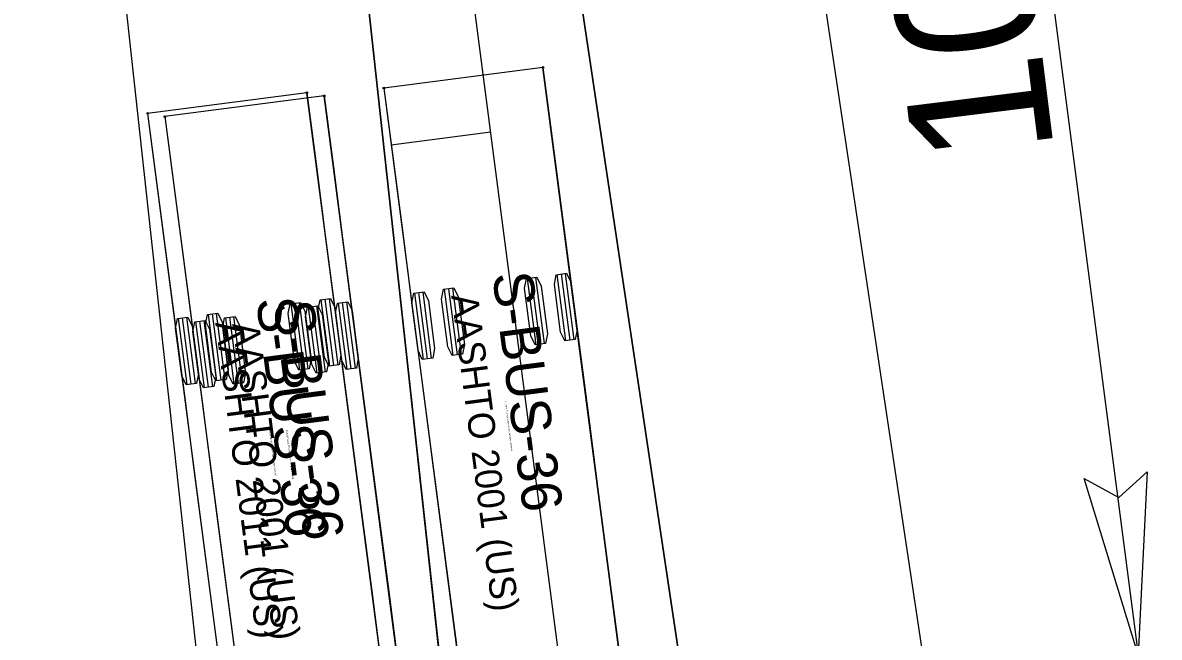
# Model space of a CAD drawing. Extents: x 2367848 to 2369479, y 800728 to 808616.
# Drawn here: x 2368338.9 to 2368395.5, y 808074.3 to 808105 of the extents above; entities that cross this region are included whole.
import ezdxf

# ---------------------------------------------------------------- set-up
doc = ezdxf.new("R2010")
doc.units = 0
for name, color, linetype in [('Prop AutoTurn Simulation', 7, 'Continuous'), ('Prop Dimension', 7, 'Continuous'), ('Prop EOT', 7, 'Continuous'), ('Prop Horizontal Alignment', 7, 'Continuous'), ('Prop Horizontal Alignment Tick Small', 7, 'Continuous'), ('Prop Lane Lines', 7, 'Continuous'), ('Prop Paint Stripe', 7, 'Continuous'), ('Prop Terminator CELL', 7, 'Continuous'), ('Scratch_Level_1', 7, 'Continuous')]:
    doc.layers.add(name, color=color, linetype=linetype)

msp = doc.modelspace()

# ---------------------------------------------------------------- linework, layer by layer
at = {"layer": 'Prop AutoTurn Simulation'}
for p, q in [((2368364.825, 808102.755), (2368356.892, 808101.723)), ((2368369.447, 808067.255), (2368364.825, 808102.755)), ((2368356.892, 808101.723), (2368361.514, 808066.222)), ((2368353.917, 808101.335), (2368345.984, 808100.302)), ((2368358.539, 808065.835), (2368353.917, 808101.335)), ((2368345.984, 808100.302), (2368350.606, 808064.802)), ((2368365.97, 808089.122), (2368365.54, 808092.428)), ((2368366.177, 808089.149), (2368365.746, 808092.455)), ((2368366.383, 808089.176), (2368365.953, 808092.482)), ((2368364.483, 808088.929), (2368364.052, 808092.234)), ((2368364.689, 808088.956), (2368364.259, 808092.261)), ((2368364.896, 808088.983), (2368364.465, 808092.288)), ((2368358.863, 808088.197), (2368358.433, 808091.503)), ((2368359.07, 808088.224), (2368358.64, 808091.53)), ((2368359.277, 808088.251), (2368358.846, 808091.556)), ((2368360.351, 808088.391), (2368359.92, 808091.696)), ((2368360.557, 808088.418), (2368360.127, 808091.723)), ((2368360.764, 808088.445), (2368360.334, 808091.75)), ((2368353.575, 808087.509), (2368353.144, 808090.814)), ((2368353.781, 808087.536), (2368353.351, 808090.841)), ((2368353.988, 808087.562), (2368353.558, 808090.868)), ((2368355.062, 808087.702), (2368354.632, 808091.008)), ((2368355.269, 808087.729), (2368354.838, 808091.035)), ((2368355.475, 808087.756), (2368355.045, 808091.062)), ((2368349.443, 808086.971), (2368349.013, 808090.276)), ((2368349.649, 808086.998), (2368349.219, 808090.303)), ((2368349.856, 808087.024), (2368349.426, 808090.33)), ((2368347.955, 808086.777), (2368347.525, 808090.082)), ((2368348.162, 808086.804), (2368347.732, 808090.109)), ((2368348.369, 808086.831), (2368347.938, 808090.136))]:
    msp.add_line(p, q, dxfattribs=at)
for points in [[(2368364.825, 808102.755), (2368365.288, 808099.205), (2368365.75, 808095.655), (2368366.212, 808092.105), (2368366.674, 808088.555), (2368367.136, 808085.005), (2368367.599, 808081.455), (2368368.061, 808077.905), (2368368.523, 808074.355), (2368368.985, 808070.805)], [(2368356.892, 808101.723), (2368357.355, 808098.173), (2368357.817, 808094.623), (2368358.279, 808091.072), (2368358.741, 808087.522), (2368359.203, 808083.972), (2368359.666, 808080.422), (2368360.128, 808076.872), (2368360.59, 808073.322)], [(2368353.917, 808101.335), (2368354.38, 808097.785), (2368354.842, 808094.235), (2368355.304, 808090.685), (2368355.766, 808087.135), (2368356.228, 808083.585), (2368356.691, 808080.035), (2368357.153, 808076.485), (2368357.615, 808072.935)], [(2368345.984, 808100.302), (2368346.447, 808096.752), (2368346.909, 808093.202), (2368347.371, 808089.652), (2368347.833, 808086.102), (2368348.295, 808082.552), (2368348.758, 808079.002), (2368349.22, 808075.452), (2368349.682, 808071.902)]]:
    msp.add_lwpolyline(points, dxfattribs=at)
for points in [[(2368366.434, 808089.183), (2368365.919, 808089.116), (2368365.703, 808089.558), (2368365.393, 808091.938), (2368365.488, 808092.421), (2368366.004, 808092.488), (2368366.22, 808092.046), (2368366.53, 808089.666)], [(2368364.947, 808088.989), (2368364.431, 808088.922), (2368364.216, 808089.365), (2368363.906, 808091.745), (2368364.001, 808092.228), (2368364.517, 808092.295), (2368364.732, 808091.852), (2368365.042, 808089.472)], [(2368359.328, 808088.258), (2368358.812, 808088.191), (2368358.597, 808088.633), (2368358.287, 808091.013), (2368358.382, 808091.496), (2368358.897, 808091.563), (2368359.113, 808091.121), (2368359.423, 808088.741)], [(2368360.815, 808088.451), (2368360.3, 808088.384), (2368360.084, 808088.827), (2368359.774, 808091.207), (2368359.869, 808091.69), (2368360.385, 808091.757), (2368360.6, 808091.314), (2368360.91, 808088.934)], [(2368354.039, 808087.569), (2368353.523, 808087.502), (2368353.308, 808087.944), (2368352.998, 808090.324), (2368353.093, 808090.807), (2368353.609, 808090.875), (2368353.824, 808090.432), (2368354.134, 808088.052)], [(2368355.527, 808087.763), (2368355.011, 808087.696), (2368354.795, 808088.138), (2368354.485, 808090.518), (2368354.581, 808091.001), (2368355.096, 808091.068), (2368355.312, 808090.626), (2368355.622, 808088.246)], [(2368349.907, 808087.031), (2368349.392, 808086.964), (2368349.176, 808087.407), (2368348.866, 808089.786), (2368348.961, 808090.269), (2368349.477, 808090.337), (2368349.693, 808089.894), (2368350.002, 808087.514)], [(2368348.42, 808086.837), (2368347.904, 808086.77), (2368347.689, 808087.213), (2368347.379, 808089.593), (2368347.474, 808090.076), (2368347.989, 808090.143), (2368348.205, 808089.7), (2368348.515, 808087.32)]]:
    msp.add_lwpolyline(points, close=True, dxfattribs=at)
for centre in [(2368364.825, 808102.755), (2368356.892, 808101.723), (2368353.917, 808101.335), (2368345.984, 808100.302)]:
    msp.add_circle(centre, 0.0417, dxfattribs=at)
at = {"layer": 'Prop Dimension'}
msp.add_line((2368381.576, 808172.631), (2368394.487, 808073.468), dxfattribs=at)
at = {"layer": 'Prop EOT'}
for p, q in [((2368339.442, 808368.833), (2368383.944, 808072.095)), ((2368348.245, 808067.447), (2368315.576, 808365.726))]:
    msp.add_line(p, q, dxfattribs=at)
at = {"layer": 'Prop Horizontal Alignment'}
msp.add_line((2368427.272, 807599.886), (2368315.244, 808460.338), dxfattribs=at)
at = {"layer": 'Prop Horizontal Alignment Tick Small'}
msp.add_line((2368362.221, 808099.52), (2368357.263, 808098.875), dxfattribs=at)
at = {"layer": 'Prop Lane Lines'}
for p, q in [((2368360.202, 808068.573), (2368327.531, 808366.851)), ((2368327.595, 808366.859), (2368372.044, 808070.546)), ((2368360.202, 808068.573), (2368349.265, 808168.424))]:
    msp.add_line(p, q, dxfattribs=at)
at = {"layer": 'Prop Paint Stripe'}
for p, q in [((2368372.044, 808070.546), (2368327.595, 808366.859)), ((2368372.044, 808070.546), (2368327.595, 808366.859)), ((2368349.265, 808168.424), (2368360.202, 808068.573))]:
    msp.add_line(p, q, dxfattribs=at)
msp.add_lwpolyline([(2368327.531, 808366.851), (2368349.265, 808168.424), (2368360.202, 808068.573)], dxfattribs=at)
at = {"layer": 'Prop Terminator CELL'}
msp.add_lwpolyline([(2368394.936, 808082.589), (2368394.487, 808073.468), (2368391.803, 808082.258), (2368393.53, 808081.31)], close=True, dxfattribs=at)
at = {"layer": 'Scratch_Level_1'}
for p, q in [((2368353.054, 808101.496), (2368345.121, 808100.463)), ((2368357.676, 808065.996), (2368353.054, 808101.496)), ((2368345.121, 808100.463), (2368349.743, 808064.963)), ((2368352.711, 808087.669), (2368352.281, 808090.975)), ((2368352.918, 808087.696), (2368352.487, 808091.002)), ((2368353.124, 808087.723), (2368352.694, 808091.029)), ((2368354.198, 808087.863), (2368353.768, 808091.168)), ((2368354.405, 808087.89), (2368353.975, 808091.195)), ((2368354.612, 808087.917), (2368354.181, 808091.222)), ((2368347.092, 808086.938), (2368346.661, 808090.243)), ((2368347.298, 808086.965), (2368346.868, 808090.27)), ((2368347.505, 808086.991), (2368347.075, 808090.297)), ((2368348.579, 808087.131), (2368348.149, 808090.437)), ((2368348.786, 808087.158), (2368348.355, 808090.464)), ((2368348.992, 808087.185), (2368348.562, 808090.491))]:
    msp.add_line(p, q, dxfattribs=at)
for points in [[(2368353.054, 808101.496), (2368353.516, 808097.946), (2368353.978, 808094.396), (2368354.44, 808090.846), (2368354.903, 808087.296), (2368355.365, 808083.746), (2368355.827, 808080.196), (2368356.289, 808076.646), (2368356.751, 808073.096)], [(2368345.121, 808100.463), (2368345.583, 808096.913), (2368346.045, 808093.363), (2368346.507, 808089.813), (2368346.969, 808086.263), (2368347.432, 808082.713), (2368347.894, 808079.163), (2368348.356, 808075.613), (2368348.818, 808072.063)]]:
    msp.add_lwpolyline(points, dxfattribs=at)
for points in [[(2368353.175, 808087.73), (2368352.66, 808087.663), (2368352.444, 808088.105), (2368352.134, 808090.485), (2368352.229, 808090.968), (2368352.745, 808091.035), (2368352.961, 808090.593), (2368353.27, 808088.213)], [(2368354.663, 808087.923), (2368354.147, 808087.856), (2368353.932, 808088.299), (2368353.622, 808090.679), (2368353.717, 808091.162), (2368354.232, 808091.229), (2368354.448, 808090.786), (2368354.758, 808088.406)], [(2368347.556, 808086.998), (2368347.041, 808086.931), (2368346.825, 808087.374), (2368346.515, 808089.753), (2368346.61, 808090.236), (2368347.126, 808090.304), (2368347.341, 808089.861), (2368347.651, 808087.481)], [(2368349.044, 808087.192), (2368348.528, 808087.125), (2368348.312, 808087.567), (2368348.002, 808089.947), (2368348.098, 808090.43), (2368348.613, 808090.497), (2368348.829, 808090.055), (2368349.139, 808087.675)]]:
    msp.add_lwpolyline(points, close=True, dxfattribs=at)
for centre in [(2368353.054, 808101.496), (2368345.121, 808100.463)]:
    msp.add_circle(centre, 0.0417, dxfattribs=at)

# ---------------------------------------------------------------- texts
at = {"layer": 'Prop AutoTurn Simulation'}
for s, height, p in [('S-BUS-36', 2, (2368362.296, 808092.443)), ('AASHTO 2001 (US)', 1.33333, (2368360.249, 808091.384)), ('S-BUS-36', 2, (2368351.388, 808091.022)), ('AASHTO 2001 (US)', 1.33333, (2368349.341, 808089.963)), ('(c) 2014 Transoft Solutions, Inc. All rights reserved.', 0.08, (2368362.92, 808086.1)), ('(c) 2014 Transoft Solutions, Inc. All rights reserved.', 0.08, (2368352.012, 808084.68))]:
    msp.add_text(s, height=height, rotation=277.418, dxfattribs=at).set_placement(p)
at = {"layer": 'Prop Dimension'}
msp.add_text("100' TAPER", height=7, rotation=97.1063, dxfattribs=at).set_placement((2368390.309, 808098.527))
at = {"layer": 'Scratch_Level_1'}
for s, height, p in [('S-BUS-36', 2, (2368350.524, 808091.183)), ('AASHTO 2011 (US)', 1.33333, (2368348.489, 808090.03)), ('(c) 2016 Transoft Solutions, Inc. All rights reserved.', 0.08, (2368351.148, 808084.841))]:
    msp.add_text(s, height=height, rotation=277.418, dxfattribs=at).set_placement(p)

doc.saveas('drawing.dxf')
